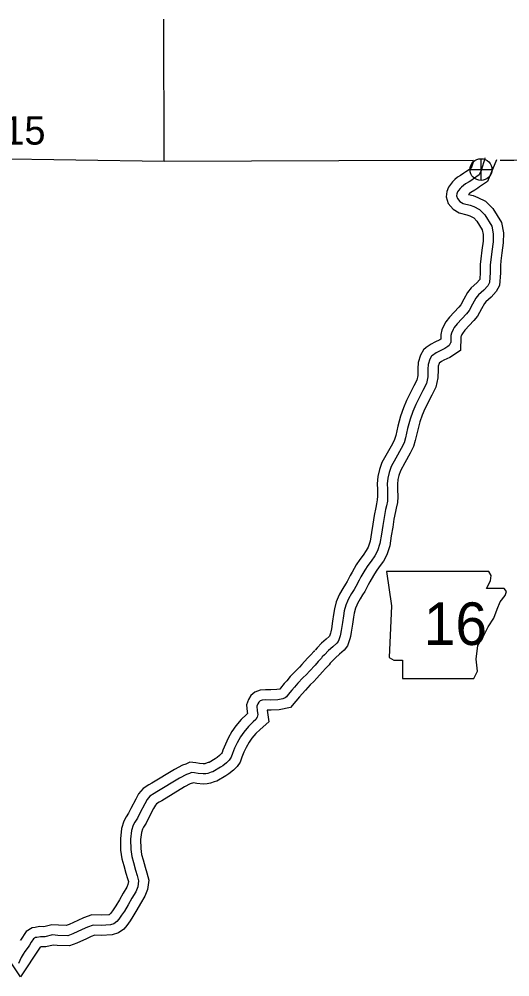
# Model space of a CAD drawing. Extents: x 31699 to 244310, y -8841 to 11474.
# Drawn here: x 98157 to 98644, y 8737 to 9687 of the extents above; entities that cross this region are included whole.
import ezdxf

# ---------------------------------------------------------------- set-up
doc = ezdxf.new("R2010")
doc.units = 0
for name, color, linetype in [('B_Logo', 7, 'Continuous'), ('G-ANNO-TEXT', 7, 'Continuous'), ('Level 21', 7, 'Continuous'), ('R_Logo', 7, 'Continuous'), ('R_XS_EARTHWORK_STAGE2', 7, 'Continuous'), ('S_WALL_ANNOT', 7, 'Continuous')]:
    doc.layers.add(name, color=color, linetype=linetype)

msp = doc.modelspace()

# ---------------------------------------------------------------- linework, layer by layer
at = {"layer": 'B_Logo'}
for points in [[(98619.55, 9549.72), (98618.92, 9547.8), (98618.08, 9544.94), (98617.17, 9541.68), (98615.72, 9537.29), (98613.93, 9532.98)], [(98613.93, 9532.98), (98608.04, 9528.92), (98606.55, 9527.74), (98604.01, 9526.05), (98600.35, 9523.86), (98598.2, 9522.52), (98596.26, 9520.85), (98594.77, 9519.4), (98593.18, 9517.41), (98592.22, 9516.04), (98591.49, 9514.08), (98591.29, 9512.06), (98592.11, 9509.49), (98594.46, 9506.62), (98597.92, 9504.67), (98604.71, 9502.82), (98608.41, 9501.41), (98614.23, 9498.53), (98619.53, 9493.36), (98626.29, 9482.02), (98627.74, 9474.45), (98627.61, 9466.3), (98626.19, 9456.89), (98625.27, 9448.51), (98624.77, 9443.55), (98624.81, 9436.07), (98624.14, 9426.16), (98622.32, 9422.89), (98618.53, 9418.62), (98613.03, 9413.89), (98610.54, 9410.67), (98607.21, 9404.75), (98603.83, 9398.29), (98601.14, 9395.12), (98591.95, 9385.19), (98589.02, 9381.29), (98587.81, 9379.44), (98586.26, 9375.99), (98585.75, 9373.36), (98585.5, 9366.67), (98585.32, 9366.33), (98584.14, 9363.69), (98582.72, 9362.44), (98579.72, 9360.53), (98574.28, 9357.88), (98571.27, 9356.24), (98567.49, 9353.78), (98566.52, 9352.88), (98564.76, 9349.88), (98563.26, 9344.89), (98562.95, 9340.06), (98562.87, 9332.51), (98561.36, 9325.85), (98557.73, 9318.98), (98550.94, 9304.92), (98547.97, 9298.07), (98545.35, 9290.63), (98542.8, 9281.06), (98540.65, 9271.84), (98539.28, 9266.91), (98536.54, 9261.27), (98531.25, 9251.94), (98526.48, 9243.37), (98524.34, 9237.62), (98523.06, 9232.03), (98522.65, 9226.2), (98522.82, 9220.93), (98522.93, 9213.71), (98522.68, 9209.16), (98521.77, 9204.39), (98520.96, 9200.89), (98519.42, 9193.02), (98518.16, 9184.82), (98516.71, 9176.36), (98515.28, 9167.22), (98512.8, 9159.72), (98510.36, 9154.9), (98506.61, 9149.69), (98503.42, 9145.38), (98500.31, 9140.73), (98496.48, 9133.92), (98494.78, 9130.79), (98491.47, 9124.4), (98489.64, 9121.4), (98487.1, 9117.44), (98484.21, 9112.27), (98483.09, 9109.89), (98481.49, 9105.96), (98479.95, 9100.16), (98479.18, 9095.33), (98478.27, 9088.61), (98477, 9080.75), (98476.32, 9077.06), (98475.85, 9075.37), (98474.58, 9071.45), (98473.83, 9069.89), (98472.42, 9068.11), (98468.61, 9064.64), (98464.28, 9060.82), (98460.22, 9056.61), (98458.17, 9054.47)], [(98458.17, 9054.47), (98457.27, 9053.37), (98454.12, 9049.93), (98450.91, 9046.48), (98445.39, 9040.28), (98442.5, 9037.18), (98438.95, 9033.85), (98433.87, 9028.34), (98430.54, 9024.42), (98427.97, 9021.53), (98424.39, 9017.2), (98422.46, 9015), (98421.17, 9013.88), (98419, 9013.08), (98414.1, 9012.11), (98407.13, 9011.75), (98401.93, 9011.84), (98398.54, 9011.66), (98396.51, 9010.93), (98395.08, 9009.68), (98394.07, 9008.04), (98393.22, 9005.61), (98393.57, 9001.07), (98394.02, 8997.41), (98393.64, 8994.86), (98392.26, 8992.34), (98389.61, 8989.98), (98385.03, 8985.56), (98380.29, 8979.99), (98376.99, 8975.2), (98373.65, 8969.41), (98371.16, 8964.05), (98368.95, 8958.56), (98367.6, 8954.91), (98365.76, 8952.24), (98363.12, 8949.48), (98359.56, 8946.56), (98357.08, 8945), (98349.64, 8940.55), (98347.86, 8940.09), (98344.7, 8938.98), (98342.72, 8938.65), (98339.93, 8938.42), (98334.99, 8938.92), (98331.44, 8939.47), (98328.44, 8939.78), (98326.54, 8938.84), (98323.31, 8937.8), (98316.57, 8934.24), (98294.06, 8920.53), (98291.18, 8919.03), (98287.08, 8916.35), (98284.26, 8913.05), (98282, 8908.77), (98277.11, 8899.58), (98274.75, 8894.56), (98272.22, 8890.73), (98270.39, 8887.53), (98268.83, 8882.27), (98267.92, 8873.69), (98268.05, 8863.6), (98269.02, 8856.42), (98270.75, 8850.46), (98272.93, 8842.91), (98274.57, 8837.49), (98275.94, 8832.32), (98275.07, 8826.28), (98273.17, 8821.47), (98269.25, 8815.06), (98265.41, 8808.52), (98261.75, 8802.32), (98259.03, 8798.15), (98256.43, 8794.26), (98254.31, 8791.85), (98251.39, 8789.68), (98247.96, 8788.63), (98238.73, 8788.12), (98230.93, 8788.4), (98225.14, 8786.33), (98219.97, 8783.89), (98210.79, 8779.71), (98205.65, 8777.87), (98195.79, 8778.21), (98190.52, 8778.7), (98182.86, 8776.78), (98178.53, 8776.9), (98174.89, 8776.18), (98173.64, 8776), (98171.48, 8774.66), (98169.33, 8771.38), (98167.7, 8768.39), (98166.23, 8766.4), (98163.17, 8762.36), (98161.39, 8759.69), (98159.31, 8756.15), (98156.65, 8750.18)]]:
    msp.add_lwpolyline(points, dxfattribs=at)
at = {"layer": 'G-ANNO-TEXT'}
msp.add_lwpolyline([(98521.79, 9139.21), (98526.87, 9105.37), (98524.61, 9054.06), (98529.12, 9051.24), (98537.58, 9051.24), (98537.58, 9033.19), (98608.64, 9033.19), (98612.02, 9040.52), (98610.89, 9052.36), (98612.58, 9065.9), (98618.79, 9076.61), (98622.73, 9084.51), (98628.37, 9092.97), (98631.76, 9101.99), (98634.58, 9109.32), (98639.65, 9115.53), (98640.78, 9119.47), (98638.52, 9122.29), (98621.04, 9122.29), (98624.99, 9130.19), (98625.55, 9135.26), (98623.22, 9139.16)], close=True, dxfattribs=at)
at = {"layer": 'Level 21'}
for p, q in [((98615.59, 9527.32), (98615.59, 9548.98)), ((98604.76, 9538.15), (98626.43, 9538.15))]:
    msp.add_line(p, q, dxfattribs=at)
msp.add_circle((98615.59, 9538.15), 10.83, dxfattribs=at)
at = {"layer": 'R_Logo'}
for points in [[(98301.18, 9546.65), (98300.95, 9687.44)], [(98101.1, 9549.28), (98125.5, 9549.12), (98301.18, 9546.65), (98474.48, 9547.13)], [(98474.48, 9547.13), (98608.07, 9547.4)], [(98634.6, 9547.45), (98648.16, 9547.48), (98821.71, 9548.66), (98997.84, 9549.01), (99055.11, 9550.2)]]:
    msp.add_lwpolyline(points, dxfattribs=at)
at = {"layer": 'R_XS_EARTHWORK_STAGE2'}
for points in [[(98608.27, 9546.99), (98607.61, 9544.6), (98605.96, 9539.63)], [(98630.9, 9547.8), (98622.03, 9526.42)], [(98605.96, 9539.63), (98602.09, 9536.97), (98600.66, 9535.83), (98598.66, 9534.51), (98595.13, 9532.39), (98592.26, 9530.6), (98589.49, 9528.22), (98587.35, 9526.12), (98585.17, 9523.4), (98583.3, 9520.72), (98581.67, 9516.36), (98581.13, 9511), (98583.16, 9504.62), (98587.93, 9498.83), (98594.09, 9495.35), (98601.6, 9493.3), (98604.4, 9492.23), (98608.38, 9490.27), (98611.61, 9487.11), (98616.8, 9478.41), (98617.72, 9473.58), (98617.62, 9467.13), (98616.27, 9458.19), (98615.32, 9449.56), (98614.76, 9444.02), (98614.81, 9436.37), (98614.32, 9429.07), (98614.12, 9428.71), (98611.5, 9425.76), (98605.74, 9420.81), (98602.18, 9416.21), (98598.42, 9409.52), (98595.49, 9403.91), (98593.66, 9401.76), (98584.26, 9391.61), (98580.82, 9387.03), (98579.01, 9384.25), (98576.67, 9379.03), (98575.79, 9374.51), (98575.61, 9369.77), (98574.83, 9369.28), (98569.7, 9366.77), (98566.14, 9364.84), (98561.31, 9361.69), (98558.65, 9359.21), (98555.53, 9353.91), (98553.35, 9346.66), (98552.96, 9340.44), (98552.88, 9333.68), (98551.9, 9329.35), (98548.8, 9323.49), (98541.84, 9309.08), (98538.65, 9301.72), (98535.79, 9293.58), (98533.1, 9283.49), (98530.96, 9274.31), (98529.89, 9270.47), (98527.68, 9265.93), (98522.53, 9256.84), (98517.37, 9247.57), (98514.74, 9240.49), (98513.14, 9233.5), (98512.64, 9226.38), (98512.83, 9220.69), (98512.93, 9213.92), (98512.73, 9210.37), (98511.99, 9206.46), (98511.18, 9202.98), (98509.57, 9194.74), (98508.29, 9186.43), (98506.84, 9177.97), (98505.53, 9169.58), (98503.54, 9163.57), (98501.79, 9160.11), (98498.53, 9155.59), (98495.24, 9151.13), (98491.79, 9145.97), (98487.72, 9138.76), (98485.95, 9135.48), (98482.75, 9129.31), (98481.15, 9126.7), (98478.52, 9122.58), (98475.31, 9116.84), (98473.93, 9113.91), (98471.99, 9109.14), (98470.16, 9102.24), (98469.29, 9096.79), (98468.38, 9090.09), (98467.14, 9082.45), (98466.57, 9079.32), (98466.27, 9078.27), (98465.28, 9075.19), (98465.08, 9074.95), (98461.94, 9072.09), (98457.36, 9068.05), (98453.02, 9063.55), (98450.96, 9061.4)], [(98622.03, 9526.42), (98613.99, 9520.88), (98612.44, 9519.65), (98609.35, 9517.59), (98605.57, 9515.33), (98604.14, 9514.43), (98603.17, 9513.6), (98607.81, 9512.34), (98612.42, 9510.58), (98620.09, 9506.79), (98627.45, 9499.6), (98635.78, 9485.63), (98637.75, 9475.32), (98637.6, 9465.47), (98636.11, 9455.6), (98635.21, 9447.46), (98634.77, 9443.08), (98634.82, 9435.76), (98633.97, 9423.24), (98630.52, 9417.07), (98625.56, 9411.48), (98620.32, 9406.97), (98618.9, 9405.13), (98616, 9399.97), (98612.17, 9392.66), (98608.62, 9388.48), (98599.64, 9378.78), (98597.21, 9375.55), (98596.62, 9374.64), (98595.86, 9372.94), (98595.71, 9372.21), (98595.21, 9358.53), (98584.6, 9351.79), (98578.87, 9348.99), (98576.4, 9347.65), (98574.21, 9346.22), (98573.99, 9345.85), (98573.17, 9343.11), (98572.95, 9339.69), (98572.86, 9331.34), (98570.82, 9322.34), (98566.65, 9314.46), (98560.03, 9300.75), (98557.28, 9294.42), (98554.91, 9287.68), (98552.51, 9278.64), (98550.34, 9269.36), (98548.67, 9263.36), (98545.39, 9256.62), (98539.97, 9247.05), (98535.58, 9239.17), (98533.94, 9234.74), (98532.98, 9230.55), (98532.66, 9226.02), (98532.82, 9221.17), (98532.93, 9213.51), (98532.63, 9207.95), (98531.56, 9202.32), (98530.74, 9198.79), (98529.27, 9191.3), (98528.03, 9183.22), (98526.58, 9174.74), (98525.03, 9164.86), (98522.06, 9155.88), (98518.93, 9149.68), (98514.68, 9143.8), (98511.6, 9139.63), (98508.84, 9135.49), (98505.23, 9129.09), (98503.62, 9126.11), (98500.18, 9119.49), (98498.12, 9116.1), (98495.69, 9112.3), (98493.11, 9107.69), (98492.25, 9105.87), (98490.99, 9102.78), (98489.75, 9098.09), (98489.07, 9093.87), (98488.16, 9087.14), (98486.85, 9079.06), (98486.07, 9074.79), (98485.42, 9072.47), (98483.2, 9065.63), (98479.77, 9061.27), (98475.28, 9057.19), (98471.2, 9053.59), (98467.43, 9049.68), (98465.37, 9047.54)], [(98450.41, 9060.79), (98449.7, 9059.91), (98446.77, 9056.71), (98443.52, 9053.21), (98438, 9047.02), (98435.41, 9044.25), (98431.84, 9040.9), (98426.38, 9034.97), (98422.99, 9030.98), (98420.38, 9028.04), (98416.77, 9023.68), (98415.87, 9022.65), (98412.87, 9022.06), (98406.96, 9021.75), (98401.76, 9021.85), (98396.54, 9021.57), (98391.33, 9019.69), (98387.36, 9016.2), (98384.99, 9012.37), (98383.09, 9006.93), (98383.62, 9000.07), (98383.84, 8998.24), (98382.81, 8997.32), (98377.73, 8992.41), (98372.35, 8986.08), (98368.52, 8980.54), (98364.76, 8974.02), (98361.98, 8968.02), (98359.62, 8962.16), (98358.66, 8959.55), (98357.98, 8958.58), (98356.31, 8956.83), (98353.71, 8954.69), (98351.86, 8953.53), (98345.74, 8949.87), (98344.95, 8949.66), (98342.2, 8948.7), (98341.48, 8948.58), (98340.03, 8948.46), (98336.26, 8948.85), (98332.71, 8949.4), (98326.59, 8950.01), (98322.78, 8948.14), (98319.4, 8947.05), (98311.63, 8942.93), (98289.15, 8929.24), (98286.13, 8927.67), (98280.41, 8923.94), (98275.93, 8918.7), (98273.16, 8913.44), (98268.17, 8904.06), (98266.01, 8899.48), (98263.69, 8895.98), (98261.13, 8891.48), (98258.99, 8884.23), (98257.91, 8874.15), (98258.06, 8862.86), (98259.21, 8854.34), (98261.14, 8847.68), (98263.34, 8840.08), (98264.95, 8834.76), (98265.75, 8831.73), (98265.34, 8828.87), (98264.19, 8825.95), (98260.68, 8820.2), (98256.79, 8813.59), (98253.26, 8807.6), (98250.69, 8803.66), (98248.48, 8800.36), (98247.5, 8799.25), (98246.81, 8798.74), (98246.2, 8798.55), (98238.63, 8798.13), (98229.38, 8798.46), (98221.32, 8795.59), (98215.76, 8792.96), (98207.02, 8788.98), (98204.08, 8787.93), (98196.43, 8788.19), (98189.74, 8788.82), (98181.76, 8786.81), (98177.69, 8786.93), (98173.23, 8786.04), (98170.15, 8785.62), (98164.33, 8781.99), (98158.63, 8773.32), (98158.39, 8773.68)], [(98465.92, 9048.15), (98464.84, 9046.84), (98461.47, 9043.14), (98458.3, 9039.74), (98452.78, 9033.55), (98449.58, 9030.11), (98446.05, 9026.81), (98441.36, 9021.71), (98438.09, 9017.86), (98435.56, 9015.02), (98432, 9010.72), (98426.44, 9004.35), (98415.34, 9002.16), (98407.3, 9001.74), (98403.55, 9001.81), (98404.98, 8990.28), (98396.41, 8982.65), (98392.33, 8978.7), (98388.23, 8973.89), (98385.45, 8969.85), (98382.53, 8964.8), (98380.34, 8960.07), (98378.28, 8954.96), (98376.55, 8950.27), (98373.54, 8945.91), (98369.94, 8942.13), (98365.41, 8938.42), (98362.31, 8936.48), (98353.54, 8931.23), (98350.77, 8930.51), (98347.2, 8929.26), (98343.95, 8928.71), (98339.82, 8928.38), (98333.71, 8929), (98330.26, 8929.54), (98327.21, 8928.55), (98321.52, 8925.54), (98298.98, 8911.81), (98296.23, 8910.38), (98293.75, 8908.76), (98292.59, 8907.41), (98290.84, 8904.09), (98286.06, 8895.1), (98283.49, 8889.64), (98280.74, 8885.49), (98279.65, 8883.59), (98278.68, 8880.3), (98277.93, 8873.22), (98278.04, 8864.34), (98278.83, 8858.49), (98280.35, 8853.24), (98282.52, 8845.75), (98284.19, 8840.22), (98286.13, 8832.92), (98284.81, 8823.69), (98282.15, 8816.99), (98277.83, 8809.92), (98274.03, 8803.45), (98270.25, 8797.04), (98267.37, 8792.64), (98264.38, 8788.15), (98261.12, 8784.45), (98255.96, 8780.62), (98249.73, 8778.71), (98238.83, 8778.11), (98232.49, 8778.34), (98228.97, 8777.08), (98224.17, 8774.82), (98214.55, 8770.44), (98207.23, 8767.81), (98195.15, 8768.23), (98191.29, 8768.59), (98183.96, 8766.74), (98179.37, 8766.87), (98178.17, 8766.64), (98158.74, 8737.07), (98142.86, 8760.91)]]:
    msp.add_lwpolyline(points, dxfattribs=at)

# ---------------------------------------------------------------- texts
at = {"layer": 'G-ANNO-TEXT'}
msp.add_text('16', height=42.24, dxfattribs=at).set_placement((98558.77, 9066.39))
at = {"layer": 'S_WALL_ANNOT'}
msp.add_text('9.15', height=28.16, dxfattribs=at).set_placement((98110.24, 9562.95))

doc.saveas('drawing.dxf')
